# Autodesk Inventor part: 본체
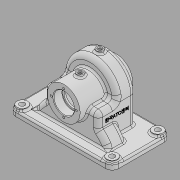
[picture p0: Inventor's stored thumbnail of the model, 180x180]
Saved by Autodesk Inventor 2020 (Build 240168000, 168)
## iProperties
Created: 2024-01
Part Number: 본체
Material: 일반
Document SubType Name: Modeling
Designer: 방송실
Density: 1 g/cm^3
Appearance: 기본값
Mass: 276.944 g
Surface Area: 911.068 cm^2
Volume: 276.944 cm^3
Author: 방송실
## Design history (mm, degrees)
sketch "스케치1"
  geometry: L1 (-88, 50)-(88, 50); L2 (88, 50)-(88, -50); L3 (88, -50)-(-88, -50); L4 (-88, -50)-(-88, 50); L5 (-88, 50)-(88, -50); L6 (88, 50)-(-88, -50); 1 further point
  constraints: 12 end point, 2 midpoint, 2 parallel, 1 horizontal, 1 perpendicular
  dimensions: "d0" = 176 distance of L1.start L1.end; "d1" = 100 distance of L1.end L2.end
extrude "돌출1" new body sketch "스케치1" distance "d2" = 9; taper "d3" = 0 deg
sketch "스케치2"
  geometry: L1 (0, 50)-(0, -50) reference; L2 (84, 45)-(56, 45); L3 (56, 45)-(56, -45); L4 (56, -45)-(84, -45); L5 (84, -45)-(84, 45); L6 (0, 50)-(9, 50) reference; 3 further points
  constraints: 8 end point, 2 midpoint, 2 parallel, 1 horizontal, 1 horizontal alignment, 1 perpendicular
  dimensions: "d4" = 56 distance between parallel lines of L3 L1; "d5" = 5 distance between parallel lines of L6 L2; "d6" = 56 diameter of L5 L3
revolve "회전1" sketch "스케치2" stored, may be unused: angle "d7" = 90 deg
node "작업 평면1"
sketch "스케치3"
  geometry: L1 (88, 9)-(-88, 9) reference; L2 (-46, 56)-(-46, 9); L3 (46, 56)-(46, 9); L4 (-46, 56)-(46, 56); C1 r 28 at (0, 56) reference; A1 r 46 centre (0, 56) between (-46, 56) and (46, 56); 1 further point
  constraints: 6 end point, 2 perpendicular, 2 point on circle, 2 point on line, 2 tangent, 1 centre point, 1 coincident, 1 vertical
  dimensions: "d9" = 92 diameter of A1
extrude "돌출2" join sketch "스케치3" distance "d10" = 32; taper "d11" = 0 deg
extrude "돌출3" join sketch "스케치3" distance "d12" = 64; taper "d13" = 0 deg
sketch "스케치4"
  geometry: L1 (88, 0)-(-88, 0) reference; C1 r 72 at (0, -24); 3 further points
  constraints: 1 centre point, 1 vertical alignment
  dimensions: "d14" = 72 radius of C1; "d15" = 48 distance edge to line of C1 L1
extrude "돌출4" join sketch "스케치4" distance "d16" = 32; taper "d17" = 0 deg
node "작업 평면2"
sketch "스케치5"
  geometry: L1 (46, 0)-(-46, 0) reference; C1 r 6 at (0, 17); C2 r 4 at (0, 17); 2 further points
  constraints: 2 centre point, 1 coincident, 1 midpoint, 1 vertical alignment
  dimensions: "d20" = 12 diameter of C1; "d21" = 8 diameter of C2; "d22" = 17 distance from line of C1.centre L1
extrude "돌출5" join sketch "스케치5" stored distance "d23" = 32; taper "d24" = 0 deg
extrude "돌출6" cut sketch "스케치5" distance "d25" = 2; taper "d26" = 0 deg
node "작업 평면3"
sketch "스케치6"
  geometry: L1 (46, 0)-(-46, 0) reference; C1 r 6 at (0, -17); C2 r 4 at (0, -17); 1 further point
  constraints: 2 centre point, 1 coincident, 1 vertical alignment
  dimensions: "d28" = 12 diameter of C1; "d29" = 8 diameter of C2; "d30" = 17 distance from line of C1.centre L1
extrude "돌출7" join sketch "스케치6" stored distance "d31" = 2; taper "d32" = 0 deg
extrude "돌출8" cut sketch "스케치6" distance "d33" = 2; taper "d34" = 0 deg
node "작업 평면4"
node "작업 평면6"
sketch "스케치8"
  geometry: L1 (-46, 56)-(-28, 56) reference; L2 (28, 56)-(46, 56) reference; L3 (-41, 51)-(-22.45, 51); L4 (22.45, 51)-(41, 51); L5 (-41, 51)-(-41, 28.991); L6 (41, 28.991)-(41, 51); L7 (88, 0)-(-88, 0) reference; L8 (-41, 28.991)-(41, 28.991); A1 r 72 centre (0, -24) between (-46, 31.39) and (-63.992, 9) reference; A2 r 72 centre (0, -24) between (63.992, 9) and (46, 31.39) reference; A3 r 67 centre (0, -24) between (-41, 28.991) and (-62.554, 0); A4 r 67 centre (0, -24) between (62.554, 0) and (41, 28.991); A5 r 28 centre (0, 56) between (28, 56) and (-28, 56) reference; A6 r 23 centre (0, 56) between (22.45, 51) and (-22.45, 51); 3 further points; 2 other entities
  constraints: 10 end point, 6 point on circle, 3 centre point, 2 point on line, 2 vertical, 2 other
  dimensions: "d40" = 5 radial gap between concentric circles of A1 A3; "d41" = 5 radial gap between concentric circles of A2 A4; "d43" = 5 radial gap between concentric circles of A5 A6; "d44" = 5 dimension on L5; "d45" = 5 dimension on L6; "d46" = 5 distance between parallel lines of L4 L2; "d47" = 5 distance between parallel lines of L3 L1
extrude "돌출10" cut sketch "스케치8" distance "d48" = 32; taper "d49" = 0 deg
node "작업 평면7"
sketch "스케치9"
  geometry: L1 (-41, 56)-(-41, -14); L2 (-41, -14)-(41, -14); L3 (41, -14)-(41, 56); A1 r 46 centre (0, 56) between (46, 56) and (-46, 56) reference; A2 r 41 centre (0, 56) between (41, 56) and (-41, 56); 1 further point
  constraints: 6 end point, 2 perpendicular, 2 point on circle, 2 tangent, 1 centre point, 1 vertical
  dimensions: "d51" = 5 radial gap between concentric circles of A1 A2; "d52" = 70 distance from line of A1.centre L2
extrude "돌출11" cut sketch "스케치9" distance "d53" = 22; taper "d54" = 0 deg
sketch "스케치10"
  geometry: L1 (28, 45)-(84, 45) reference; L2 (28, -45)-(84, -45) reference; L3 (56, 45)-(56, -45); L4 (73.5, 45)-(73.5, 30); L5 (73.5, 30)-(70.5, 30); L6 (70.5, 30)-(70.5, -30); L7 (70.5, -30)-(73.5, -30); L8 (73.5, -30)-(73.5, -45); 1 further point
  constraints: 12 end point, 4 perpendicular, 2 midpoint, 2 point on line, 1 vertical
  dimensions: "d55" = 29 diameter of L6 L3; "d56" = 35 diameter of L8 L3; "d57" = 15 distance of L7.end L8.end; "d58" = 35 diameter of L4 L3; "d59" = 15 distance of L4.start L4.end
node "작업 평면8"
sketch "스케치11"
  geometry: L1 (-41, 0)-(-41, 56) reference; L2 (41, 56)-(41, 0) reference; L3 (41, 28.991)-(-41, 28.991) reference; L4 (88, 0)-(-88, 0) reference; A1 r 72 centre (0, -24) between (-46, 31.39) and (-63.992, 9) reference; A2 r 72 centre (0, -24) between (63.992, 9) and (46, 31.39) reference; A3 r 67 centre (0, -24) between (-41, 28.991) and (-62.554, 0); A4 r 67 centre (0, -24) between (62.554, 0) and (41, 28.991); 1 further point
  constraints: 4 point on circle, 4 point on line, 2 centre point
  dimensions: "d61" = 5 radial gap between concentric circles of A1 A3; "d62" = 5 radial gap between concentric circles of A2 A4
extrude "돌출12" cut sketch "스케치11" distance "d63" = 22; taper "d64" = 0 deg
extrude "돌출13" cut sketch "스케치11" distance "d65" = 32; taper "d66" = 0 deg
revolve "회전2" stored, may be unused: angle "d67" = 90 deg
sketch "스케치12"
  geometry: C1 r 4 at (0, 0) reference; 2 further points
  constraints: 1 coincident
hole "구멍1" sketch "스케치12" at (0, 0) diameter "d68" = 5.1881; stored, may be unused: countersink angle "d72" = 90 deg, drill point angle "d74" = 0 deg; dims "d69" = 12, "d70" = 4, "d71" = 2, "d73" = 16
sketch "스케치13"
  geometry: C1 r 4 at (0, 0) reference; 2 further points
  constraints: 1 coincident
hole "구멍2" sketch "스케치13" at (0, 0) diameter "d75" = 5.1881; stored, may be unused: countersink angle "d79" = 90 deg, drill point angle "d81" = 0 deg; dims "d76" = 12, "d77" = 4, "d78" = 2, "d80" = 16
sketch "스케치14" dims "d82" = 43
  geometry: L1 (0, 0)-(0, 21.5); C1 r 28 at (0, 0) reference; 2 further points
  constraints: 2 coincident, 2 end point, 1 vertical, 1 vertical alignment, 2 other
hole "구멍3" sketch "스케치14" at (0, 21.5) diameter "d83" = 3.45873; stored, may be unused: countersink angle "d87" = 90 deg, drill point angle "d89" = 118 deg; dims "d84" = 8, "d85" = 4, "d86" = 2, "d88" = 10
sketch "스케치15" dims "d93" = 43
  geometry: L1 (0, 0)-(0, 21.5); C1 r 28 at (0, 0) reference; 2 further points
  constraints: 2 coincident, 2 end point, 1 vertical, 1 vertical alignment, 2 other
hole "구멍4" sketch "스케치15" at (0, 21.5) diameter "d94" = 3.45873; stored, may be unused: countersink angle "d98" = 90 deg, drill point angle "d100" = 118 deg; dims "d95" = 8, "d96" = 4, "d97" = 2, "d99" = 10
fillet "모깎기1" dims "d104" = 11
sketch "스케치16"
  geometry: L1 (77, -39)-(-77, -39); L2 (-77, -39)-(-77, 39); L3 (-77, 39)-(77, 39); L4 (77, 39)-(77, -39); L5 (77, -39)-(-77, 39); L6 (-77, -39)-(77, 39); C1 r 9 at (-77, 39); C2 r 9 at (77, 39); C3 r 9 at (77, -39); C4 r 9 at (-77, -39); 1 further point
  constraints: 12 end point, 4 centre point, 4 coincident, 2 midpoint, 2 parallel, 1 horizontal, 1 perpendicular
  dimensions: "d105" = 154 distance of L2.end L3.end; "d106" = 78 distance of L1.end L2.end; "d107" = 18 diameter of C1; "d108" = 18 diameter of C2; "d109" = 18 diameter of C3; "d110" = 18 diameter of C4
extrude "돌출14" join sketch "스케치16" distance "d111" = 4; taper "d112" = 0 deg
sketch "스케치17"
  geometry: C1 r 9 at (0, 0) reference; C2 r 9 at (0, -78) reference; C3 r 9 at (154, -78) reference; C4 r 9 at (154, 0) reference; 5 further points
  constraints: 4 coincident
hole "구멍5" sketch "스케치17" at (0, 0), (0, -78), (154, -78), (154, 0) diameter "d113" = 9; stored, may be unused: countersink angle "d117" = 90 deg, drill point angle "d119" = 118 deg; dims "d114" = 8, "d115" = 4, "d116" = 2, "d118" = 10
sketch "스케치18"
  geometry: L1 (-82, 0)-(-82, -9) reference; L2 (-71, -9)-(7, -9) reference; 2 further points
  constraints: 1 other
  dimensions: "d120" = 50 distance from line of point (-32, 31) L1; "d121" = 40 distance from line of point (-32, 31) L2
feature "엠보싱1" sketch "스케치18" dims "d122" = 0.5, "d123" = 0
fillet "모깎기3" dims "d125" = 3
fillet "모깎기4" dims "d126" = 0.6, "d127" = 3, "d128" = 5
fillet "모깎기5" dims "d129" = 3
chamfer "모따기1" distance "d130" = 1; stored, may be unused: second distance "d131" = 2, angle "d132" = 45 deg
fillet "모깎기7" dims "d134" = 8
fillet "모깎기8" dims "d135" = 3
fillet "모깎기9" dims "d136" = 3
fillet "모깎기10" dims "d137" = 8
fillet "모깎기11" dims "d138" = 8
fillet "모깎기12" dims "d139" = 8
fillet "모깎기13" dims "d140" = 3
fillet "모깎기14" dims "d141" = 3
fillet "모깎기15" dims "d142" = 3
node "솔리드1"
pattern_circular "원형 패턴1" dims angle "d91" = 360 deg
pattern_circular "원형 패턴2" dims angle "d102" = 360 deg
feature "A9D066F2-1C7D-4E18-AEED-F7BC21143FA4" dims "d113" = 9, "d114" = 8, "d115" = 4, "d116" = 2, "d117" = 90 deg, "d118" = 10, "d119" = 118 deg
other parameters: "d8" = -32, "d18" = 88, "d27" = 106, "d39" = -5, "d50" = -5, "d60" = -5
